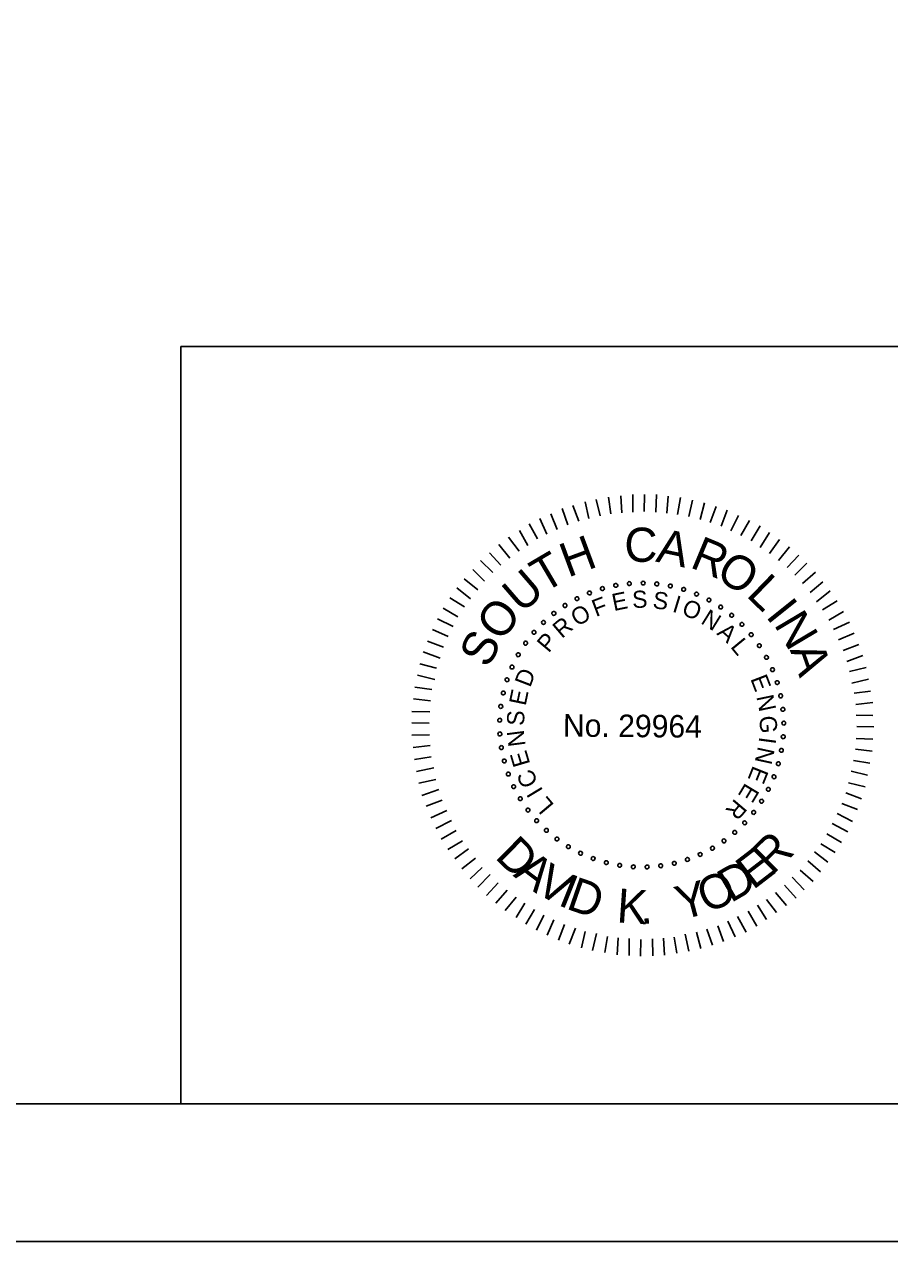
# Model space of a CAD drawing. Extents: x -133.1 to -97, y -1.7 to 20.6.
# Drawn here: x -111.075 to -107.934, y -1.691 to 2.729 of the extents above; entities that cross this region are included whole.
import ezdxf

# ---------------------------------------------------------------- set-up
doc = ezdxf.new("R2010")
doc.units = 0
for name, color, linetype in [('BR_BORDER LINES', 7, 'Continuous'), ('BR_TEXT', 7, 'Continuous'), ('Level 31', 7, 'Continuous')]:
    doc.layers.add(name, color=color, linetype=linetype)

msp = doc.modelspace()

# ---------------------------------------------------------------- linework, layer by layer
at = {"layer": 'BR_BORDER LINES'}
for p, q in [((-110.5071, 1.5591), (-105.1419, 1.5591)), ((-110.5071, -1.191), (-110.5071, 1.5591)), ((-131.3076, -1.191), (-97.6416, -1.191))]:
    msp.add_line(p, q, dxfattribs=at)
at = {"layer": 'BR_TEXT'}
for p, q in [((-108.9059, 0.9561), (-108.9097, 1.017)), ((-108.8664, 0.9584), (-108.8658, 1.0227)), ((-108.8243, 0.9606), (-108.8238, 1.0224)), ((-108.7823, 0.9577), (-108.78, 1.022)), ((-109.0623, 0.9248), (-109.0842, 0.9824)), ((-109.0262, 0.9348), (-109.0394, 0.9958)), ((-108.9849, 0.9447), (-108.999, 1.0041)), ((-108.9454, 0.9521), (-108.9543, 1.0131)), ((-108.742, 0.9548), (-108.7372, 1.0156)), ((-108.7034, 0.9501), (-108.6926, 1.011)), ((-108.6631, 0.9421), (-108.6489, 1.0012)), ((-108.622, 0.9314), (-108.606, 0.9922)), ((-108.5852, 0.9208), (-108.5633, 0.9781)), ((-109.1777, 0.8785), (-109.2039, 0.9345)), ((-109.1406, 0.8954), (-109.1642, 0.9514)), ((-109.1019, 0.9122), (-109.1229, 0.9708)), ((-108.5458, 0.9076), (-108.5239, 0.9658)), ((-108.5099, 0.8902), (-108.482, 0.9457)), ((-109.2475, 0.8371), (-109.278, 0.8914)), ((-109.2122, 0.8608), (-109.2426, 0.9151)), ((-108.474, 0.8727), (-108.4427, 0.9282)), ((-108.4364, 0.8544), (-108.4042, 0.9082)), ((-109.3123, 0.7904), (-109.3522, 0.8405)), ((-109.2786, 0.8159), (-109.3177, 0.8668)), ((-108.4031, 0.8301), (-108.3692, 0.8839)), ((-108.3699, 0.8083), (-108.3334, 0.8587)), ((-109.3451, 0.7658), (-109.3868, 0.8107)), ((-108.3375, 0.7824), (-108.2968, 0.8318)), ((-108.3059, 0.7572), (-108.2627, 0.8014)), ((-109.3745, 0.7386), (-109.4188, 0.7827)), ((-108.2779, 0.7295), (-108.2346, 0.7729)), ((-109.4291, 0.6763), (-109.4786, 0.7154)), ((-109.4039, 0.7079), (-109.4474, 0.7503)), ((-108.2498, 0.6984), (-108.2022, 0.74)), ((-109.4551, 0.6431), (-109.5046, 0.683)), ((-108.2226, 0.6664), (-108.1759, 0.7046)), ((-108.1988, 0.6327), (-108.1496, 0.6718)), ((-109.4768, 0.6141), (-109.5306, 0.6472)), ((-108.1768, 0.6034), (-108.1242, 0.6355)), ((-109.5012, 0.5774), (-109.5549, 0.6096)), ((-108.1548, 0.5663), (-108.1013, 0.5976)), ((-109.5361, 0.5065), (-109.5933, 0.5318)), ((-109.5186, 0.5432), (-109.575, 0.5711)), ((-108.137, 0.5318), (-108.0793, 0.5588)), ((-109.5536, 0.468), (-109.6117, 0.4899)), ((-108.1193, 0.4948), (-108.0624, 0.5192)), ((-109.5659, 0.4278), (-109.6275, 0.4506)), ((-108.1025, 0.456), (-108.0456, 0.477)), ((-109.5782, 0.3918), (-109.639, 0.4069)), ((-108.0891, 0.4156), (-108.0314, 0.4374)), ((-109.5854, 0.3498), (-109.6479, 0.3658)), ((-108.079, 0.3794), (-108.0189, 0.3935)), ((-109.596, 0.3138), (-109.6569, 0.3221)), ((-108.0708, 0.3373), (-108.0106, 0.3522)), ((-109.6006, 0.2727), (-109.6624, 0.2801)), ((-108.0625, 0.3012), (-108.0033, 0.3084)), ((-108.056, 0.26), (-107.995, 0.2663)), ((-109.6035, 0.2333), (-109.6679, 0.2338)), ((-109.6056, 0.1921), (-109.6682, 0.1926)), ((-108.0546, 0.2205), (-107.9945, 0.22)), ((-108.0524, 0.1793), (-107.9915, 0.1788)), ((-109.6042, 0.1492), (-109.6686, 0.148)), ((-108.0553, 0.1364), (-107.9952, 0.1342)), ((-109.602, 0.1105), (-109.6638, 0.1033)), ((-108.0574, 0.0978), (-107.9965, 0.0896)), ((-109.598, 0.0693), (-109.659, 0.0604)), ((-108.0645, 0.0566), (-108.0054, 0.0467)), ((-109.5881, 0.0297), (-109.6508, 0.0165)), ((-108.0735, 0.0172), (-108.0135, 0.003)), ((-109.5815, -0.0124), (-109.6426, -0.0265)), ((-108.0824, -0.0248), (-108.0224, -0.0398)), ((-109.5698, -0.0493), (-109.6318, -0.0703)), ((-109.5582, -0.0881), (-109.6167, -0.1091)), ((-108.093, -0.0615), (-108.0357, -0.0835)), ((-109.5413, -0.1251), (-109.599, -0.1521)), ((-108.107, -0.1001), (-108.0506, -0.122)), ((-109.5244, -0.1613), (-109.5813, -0.1909)), ((-108.1428, -0.1727), (-108.0856, -0.2032)), ((-108.1245, -0.1368), (-108.0681, -0.1647)), ((-109.5076, -0.1984), (-109.5619, -0.2297)), ((-108.1612, -0.2095), (-108.1082, -0.2417)), ((-109.4838, -0.2355), (-109.5382, -0.2668)), ((-109.4626, -0.2648), (-109.5127, -0.3013)), ((-108.1838, -0.2462), (-108.1317, -0.2784)), ((-109.4372, -0.2985), (-109.4873, -0.3376)), ((-108.2306, -0.3084), (-108.1846, -0.3483)), ((-108.2063, -0.2752), (-108.1577, -0.3125)), ((-109.4125, -0.3321), (-109.4567, -0.373)), ((-108.2583, -0.3417), (-108.2115, -0.3833)), ((-109.3836, -0.3582), (-109.4286, -0.4032)), ((-109.3547, -0.3884), (-109.3971, -0.4344)), ((-108.3155, -0.397), (-108.273, -0.4437)), ((-108.2869, -0.3672), (-108.2444, -0.413)), ((-109.3222, -0.4144), (-109.363, -0.4613)), ((-109.289, -0.4404), (-109.3289, -0.4882)), ((-108.3474, -0.4225), (-108.3075, -0.47)), ((-109.2583, -0.4622), (-109.2896, -0.5142)), ((-109.2233, -0.4847), (-109.2546, -0.5386)), ((-108.4139, -0.4691), (-108.3808, -0.5217)), ((-108.3802, -0.448), (-108.3446, -0.4963)), ((-109.1891, -0.5048), (-109.2162, -0.5603)), ((-109.1523, -0.5222), (-109.1769, -0.5778)), ((-108.5216, -0.5274), (-108.4947, -0.5835)), ((-108.4855, -0.5106), (-108.455, -0.5666)), ((-108.4475, -0.4911), (-108.4162, -0.5455)), ((-109.1139, -0.5397), (-109.1358, -0.5962)), ((-109.0745, -0.552), (-109.0973, -0.6102)), ((-109.0386, -0.5644), (-109.0528, -0.6235)), ((-108.9974, -0.5716), (-109.0126, -0.6333)), ((-108.6756, -0.5742), (-108.6624, -0.6361)), ((-108.6344, -0.5677), (-108.6194, -0.627)), ((-108.5974, -0.556), (-108.5764, -0.6145)), ((-108.5578, -0.5443), (-108.5368, -0.6011)), ((-108.9581, -0.5831), (-108.968, -0.6413)), ((-108.9186, -0.5877), (-108.9234, -0.6494)), ((-108.8792, -0.5906), (-108.8797, -0.6524)), ((-108.8372, -0.5935), (-108.8377, -0.6544)), ((-108.7951, -0.5913), (-108.7939, -0.6531)), ((-108.7547, -0.589), (-108.7509, -0.6509)), ((-108.7161, -0.5851), (-108.7062, -0.6435))]:
    msp.add_line(p, q, dxfattribs=at)
for centre, start, end in [((-108.8286, 0.7006), 359.5268, 179.5268), ((-109.0235, 0.6646), 21.6807, 201.6807), ((-109.0235, 0.6646), 201.6807, 21.6807), ((-108.9763, 0.6806), 16.1422, 196.1422), ((-108.9763, 0.6806), 196.1422, 16.1422), ((-108.9278, 0.692), 10.6038, 190.6038), ((-108.9278, 0.692), 190.6038, 10.6038), ((-108.8784, 0.6987), 5.0653, 185.0653), ((-108.8784, 0.6987), 185.0653, 5.0653), ((-108.8286, 0.7006), 179.5268, 359.5268), ((-108.7789, 0.6977), 173.9884, 353.9884), ((-108.7789, 0.6977), 353.9884, 173.9884), ((-108.7296, 0.69), 168.4499, 348.4499), ((-108.7296, 0.69), 348.4499, 168.4499), ((-108.6814, 0.6776), 162.9114, 342.9114), ((-108.6814, 0.6776), 342.9114, 162.9114), ((-108.6345, 0.6606), 157.373, 337.373), ((-108.6345, 0.6606), 337.373, 157.373), ((-109.1121, 0.6192), 32.7576, 212.7576), ((-109.1121, 0.6192), 212.7576, 32.7576), ((-109.0689, 0.644), 27.2191, 207.2191), ((-109.0689, 0.644), 207.2191, 27.2191), ((-108.5896, 0.6391), 151.8345, 331.8345), ((-108.5896, 0.6391), 331.8345, 151.8345), ((-108.5469, 0.6134), 326.2961, 146.2961), ((-109.1527, 0.5903), 38.2961, 218.2961), ((-109.1527, 0.5903), 218.2961, 38.2961), ((-108.5469, 0.6134), 146.2961, 326.2961), ((-108.5069, 0.5837), 140.7576, 320.7576), ((-108.5069, 0.5837), 320.7576, 140.7576), ((-109.1903, 0.5577), 43.8345, 223.8345), ((-109.1903, 0.5577), 223.8345, 43.8345), ((-108.4699, 0.5503), 135.2191, 315.2191), ((-108.4699, 0.5503), 315.2191, 135.2191), ((-109.2553, 0.4822), 54.9114, 234.9114), ((-109.2553, 0.4822), 234.9114, 54.9114), ((-109.2246, 0.5215), 49.373, 229.373), ((-109.2246, 0.5215), 229.373, 49.373), ((-108.4363, 0.5134), 129.6807, 309.6807), ((-108.4363, 0.5134), 309.6807, 129.6807), ((-109.282, 0.4402), 60.4499, 240.4499), ((-109.282, 0.4402), 240.4499, 60.4499), ((-108.4065, 0.4735), 124.1422, 304.1422), ((-108.4065, 0.4735), 304.1422, 124.1422), ((-109.3045, 0.3957), 65.9884, 245.9884), ((-109.3045, 0.3957), 245.9884, 65.9884), ((-108.3806, 0.4309), 118.6038, 298.6038), ((-108.3806, 0.4309), 298.6038, 118.6038), ((-109.3227, 0.3493), 71.5268, 251.5268), ((-109.3227, 0.3493), 251.5268, 71.5268), ((-108.359, 0.3861), 113.0653, 293.0653), ((-108.359, 0.3861), 293.0653, 113.0653), ((-108.3418, 0.3393), 107.5268, 287.5268), ((-108.3418, 0.3393), 287.5268, 107.5268), ((-109.3363, 0.3014), 77.0653, 257.0653), ((-109.3363, 0.3014), 257.0653, 77.0653), ((-108.3292, 0.2911), 101.9884, 281.9884), ((-108.3292, 0.2911), 281.9884, 101.9884), ((-109.3452, 0.2524), 82.6038, 262.6038), ((-109.3452, 0.2524), 262.6038, 82.6038), ((-108.3213, 0.2419), 96.4499, 276.4499), ((-108.3213, 0.2419), 276.4499, 96.4499), ((-109.3493, 0.2027), 88.1422, 268.1422), ((-109.3493, 0.2027), 268.1422, 88.1422), ((-108.3182, 0.1921), 90.9114, 270.9114), ((-108.3182, 0.1921), 270.9114, 90.9114), ((-109.3486, 0.1529), 93.6807, 273.6807), ((-109.3486, 0.1529), 273.6807, 93.6807), ((-108.3199, 0.1423), 85.373, 265.373), ((-108.3199, 0.1423), 265.373, 85.373), ((-109.3431, 0.1033), 99.2191, 279.2191), ((-109.3431, 0.1033), 279.2191, 99.2191), ((-108.3265, 0.0929), 79.8345, 259.8345), ((-108.3265, 0.0929), 259.8345, 79.8345), ((-109.3328, 0.0546), 104.7576, 284.7576), ((-109.3328, 0.0546), 284.7576, 104.7576), ((-108.3377, 0.0444), 74.2961, 254.2961), ((-108.3377, 0.0444), 254.2961, 74.2961), ((-109.3179, 0.007), 110.2961, 290.2961), ((-109.3179, 0.007), 290.2961, 110.2961), ((-108.3536, -0.0028), 68.7576, 248.7576), ((-108.3536, -0.0028), 248.7576, 68.7576), ((-109.2985, -0.0389), 115.8345, 295.8345), ((-109.2985, -0.0389), 295.8345, 115.8345), ((-108.374, -0.0483), 63.2191, 243.2191), ((-108.374, -0.0483), 243.2191, 63.2191), ((-109.2747, -0.0826), 121.373, 301.373), ((-109.2747, -0.0826), 301.373, 121.373), ((-108.3986, -0.0916), 57.6807, 237.6807), ((-108.3986, -0.0916), 237.6807, 57.6807), ((-109.2468, -0.1239), 126.9114, 306.9114), ((-109.2468, -0.1239), 306.9114, 126.9114), ((-108.4273, -0.1323), 52.1422, 232.1422), ((-108.4273, -0.1323), 232.1422, 52.1422), ((-109.2151, -0.1624), 132.4499, 312.4499), ((-109.2151, -0.1624), 312.4499, 132.4499), ((-108.4599, -0.1701), 46.6038, 226.6038), ((-108.4599, -0.1701), 226.6038, 46.6038), ((-109.1798, -0.1975), 137.9884, 317.9884), ((-109.1798, -0.1975), 317.9884, 137.9884), ((-108.4959, -0.2045), 41.0653, 221.0653), ((-108.4959, -0.2045), 221.0653, 41.0653), ((-109.1413, -0.2291), 143.5268, 323.5268), ((-109.1413, -0.2291), 323.5268, 143.5268), ((-109.0999, -0.2569), 149.0653, 329.0653), ((-109.0999, -0.2569), 329.0653, 149.0653), ((-108.577, -0.2622), 29.9884, 209.9884), ((-108.577, -0.2622), 209.9884, 29.9884), ((-108.5351, -0.2353), 35.5268, 215.5268), ((-108.5351, -0.2353), 215.5268, 35.5268), ((-109.056, -0.2805), 154.6038, 334.6038), ((-109.056, -0.2805), 334.6038, 154.6038), ((-109.01, -0.2997), 160.1422, 340.1422), ((-109.01, -0.2997), 340.1422, 160.1422), ((-108.9624, -0.3145), 345.6807, 165.6807), ((-108.6677, -0.3032), 18.9114, 198.9114), ((-108.6677, -0.3032), 198.9114, 18.9114), ((-108.6214, -0.2849), 24.4499, 204.4499), ((-108.6214, -0.2849), 204.4499, 24.4499), ((-108.9624, -0.3145), 165.6807, 345.6807), ((-108.9136, -0.3245), 171.2191, 351.2191), ((-108.9136, -0.3245), 351.2191, 171.2191), ((-108.8641, -0.3299), 356.7576, 176.7576), ((-108.8641, -0.3299), 176.7576, 356.7576), ((-108.8142, -0.3304), 2.2961, 182.2961), ((-108.8142, -0.3304), 182.2961, 2.2961), ((-108.7646, -0.3261), 7.8345, 187.8345), ((-108.7646, -0.3261), 187.8345, 7.8345), ((-108.7156, -0.317), 13.373, 193.373), ((-108.7156, -0.317), 193.373, 13.373)]:
    msp.add_arc(centre, 0.00701, start, end, dxfattribs=at)
at = {"layer": 'Level 31'}
msp.add_lwpolyline([(-133.1409, -1.691), (-97.141, -1.691), (-97.141, 20.309), (-133.1409, 20.309)], close=True, dxfattribs=at)

# ---------------------------------------------------------------- texts
at = {"layer": 'BR_TEXT'}
for s, height, rotation, p in [('C', 0.1241, 359.5482, (-108.8971, 0.7782)), ('A', 0.1241, 348.1981, (-108.7857, 0.779)), ('H', 0.1241, 20.3637, (-109.1015, 0.7199)), ('R', 0.1241, 337.4344, (-108.6624, 0.7591)), ('T', 0.1241, 30.4992, (-109.1894, 0.6624)), ('O', 0.1239, 326.5869, (-108.5702, 0.7224)), ('U', 0.1241, 40.8022, (-109.2706, 0.5876)), ('L', 0.1241, 315.9488, (-108.4576, 0.6546)), ('E', 0.0622, 11.4103, (-108.9351, 0.5987)), ('S', 0.0622, 2.208, (-108.8672, 0.6097)), ('S', 0.0622, 352.6608, (-108.796, 0.6095)), ('O', 0.1241, 52.0267, (-109.3451, 0.4837)), ('F', 0.0622, 20.6127, (-109.0002, 0.577)), ('I', 0.0622, 343.1136, (-108.7257, 0.5975)), ('O', 0.0622, 338.4392, (-108.6923, 0.5873)), ('I', 0.1241, 308.6613, (-108.3862, 0.5803)), ('O', 0.0622, 30.8477, (-109.0676, 0.541)), ('N', 0.0622, 328.2042, (-108.6227, 0.5559)), ('N', 0.1241, 300.7037, (-108.3556, 0.5509)), ('R', 0.0622, 40.3949, (-109.1237, 0.4971)), ('A', 0.0622, 318.657, (-108.5637, 0.5159)), ('S', 0.1239, 63.2511, (-109.3905, 0.3881)), ('P', 0.0622, 49.9421, (-109.1718, 0.4445)), ('L', 0.0622, 309.4546, (-108.5139, 0.4686)), ('A', 0.1241, 289.4792, (-108.2964, 0.4579)), ('D', 0.0622, 69.0364, (-109.2388, 0.3192)), ('E', 0.0622, 291.049, (-108.44, 0.3533)), ('E', 0.0622, 78.2388, (-109.2553, 0.2526)), ('N', 0.0622, 281.8466, (-108.4179, 0.2882)), ('S', 0.0622, 87.786, (-109.2611, 0.1815)), ('No. 29964', 0.08175, 359.5268, (-109.1199, 0.1431)), ('G', 0.0622, 272.2995, (-108.4061, 0.2179)), ('N', 0.0622, 97.3332, (-109.2549, 0.1105)), ('I', 0.0622, 262.4084, (-108.4065, 0.1441)), ('E', 0.0622, 106.5355, (-109.2379, 0.044)), ('N', 0.0622, 257.7339, (-108.411, 0.1095)), ('C', 0.0622, 116.4266, (-109.208, -0.0235)), ('E', 0.0622, 248.1867, (-108.4291, 0.0406)), ('I', 0.0622, 121.1011, (-109.1899, -0.0534)), ('E', 0.0622, 238.9844, (-108.457, -0.0222)), ('L', 0.0622, 129.9595, (-109.1493, -0.1056)), ('R', 0.0622, 229.782, (-108.4947, -0.0797)), ('D', 0.1236, 315.4053, (-109.3698, -0.2962)), ('R', 0.1236, 44.5947, (-108.3589, -0.3617)), ('E', 0.1236, 37.5339, (-108.4295, -0.4156)), ('A', 0.1236, 322.8377, (-109.3032, -0.3618)), ('V', 0.1236, 330.5179, (-109.226, -0.42)), ('O', 0.1236, 22.4212, (-108.5997, -0.4996)), ('D', 0.1236, 30.1015, (-108.5104, -0.4626)), ('I', 0.1236, 338.1981, (-109.1418, -0.4674)), ('D', 0.1236, 340.7995, (-109.1119, -0.4808)), ('Y', 0.1236, 14.8649, (-108.6915, -0.5241)), ('K', 0.1236, 356.098, (-108.9267, -0.5314)), ('.', 0.1236, 3.1588, (-108.838, -0.5377))]:
    msp.add_text(s, height=height, rotation=rotation, dxfattribs=at).set_placement(p)

doc.saveas('drawing.dxf')
